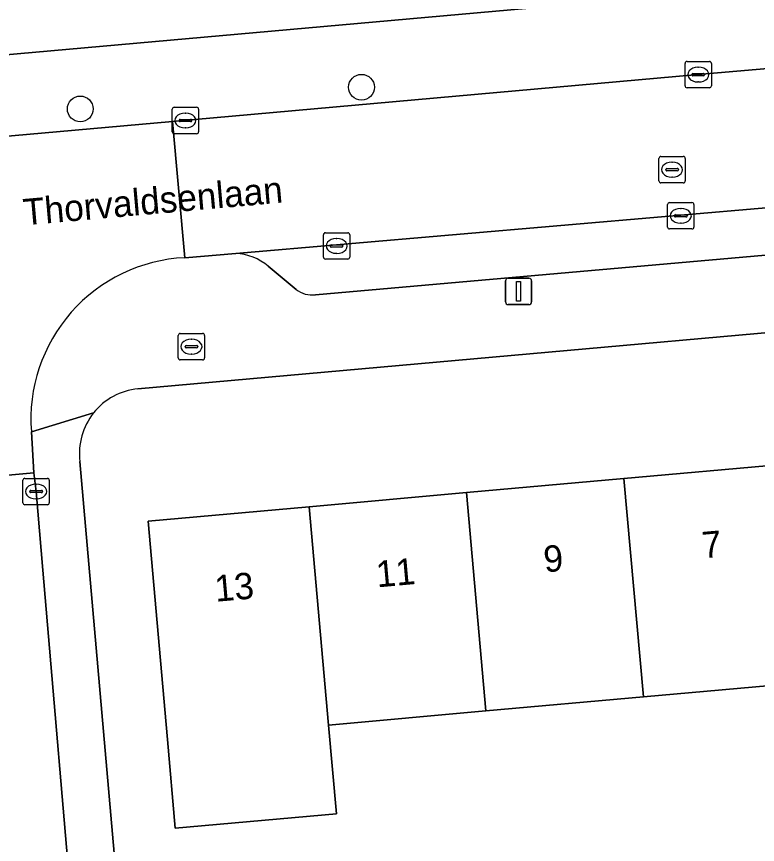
# Model space of a CAD drawing. Extents: x 160554 to 161248, y 385329 to 386506.
# Drawn here: x 161069.93 to 161098.06, y 385604.02 to 385635.43 of the extents above; entities that cross this region are included whole.
import ezdxf

# ---------------------------------------------------------------- set-up
doc = ezdxf.new("R2010")
doc.units = 0
for name, color, linetype in [('IMGEO_Boom', 7, 'Continuous'), ('IMGEO_Brandkraan', 7, 'Continuous'), ('IMGEO_Erf', 7, 'Continuous'), ('IMGEO_Kolk', 7, 'Continuous'), ('IMGEO_Lichtmast', 7, 'Continuous'), ('IMGEO_Openbare_ruimte_label', 7, 'Continuous'), ('IMGEO_Pand', 7, 'Continuous'), ('IMGEO_Pand_nummerreeks', 7, 'Continuous'), ('IMGEO_Parkeervlak_open', 7, 'Continuous'), ('IMGEO_Rijbaan_lokaal_open', 7, 'Continuous'), ('IMGEO_Rioolput', 7, 'Continuous'), ('IMGEO_Voetpad_open', 7, 'Continuous')]:
    doc.layers.add(name, color=color, linetype=linetype)

msp = doc.modelspace()

# ---------------------------------------------------------------- linework, layer by layer
at = {"layer": 'IMGEO_Boom'}
for centre in [(161083.027, 385632.744), (161072.352, 385631.921)]:
    msp.add_circle(centre, 0.489, dxfattribs=at)
at = {"layer": 'IMGEO_Brandkraan'}
for p, q in [((161076.071, 385622.476), (161076.071, 385623.328)), ((161076.146, 385623.402), (161076.998, 385623.402)), ((161076.559, 385623.182), (161076.584, 385623.182)), ((161077.072, 385623.328), (161077.072, 385622.476)), ((161076.33, 385622.896), (161076.33, 385622.908)), ((161076.373, 385622.945), (161076.771, 385622.945)), ((161076.814, 385622.908), (161076.814, 385622.896)), ((161076.768, 385622.859), (161076.37, 385622.859)), ((161076.582, 385622.622), (161076.557, 385622.622)), ((161076.998, 385622.402), (161076.146, 385622.402))]:
    msp.add_line(p, q, dxfattribs=at)
for points in [[(161076.071, 385622.476), (161076.071, 385623.328)], [(161076.146, 385623.402), (161076.998, 385623.402)], [(161077.072, 385623.328), (161077.072, 385622.476)], [(161076.998, 385622.402), (161076.146, 385622.402)]]:
    msp.add_lwpolyline(points, dxfattribs=at)
for centre, radius, start, end in [((161076.148, 385623.326), 0.0765, 91.552, 178.448), ((161076.148, 385623.326), 0.0765, 91.552, 178.448), ((161076.996, 385623.326), 0.0765, 1.552, 88.448), ((161076.996, 385623.326), 0.0765, 1.552, 88.448), ((161076.37, 385622.905), 0.0403, 85.8775, 175.7526), ((161076.367, 385622.895), 0.0366, 178.938, 274.7102), ((161076.771, 385622.902), 0.043, 264.8664, 352.4533), ((161076.775, 385622.907), 0.0386, 1.7309, 96.639), ((161076.148, 385622.478), 0.0765, 181.552, 268.448), ((161076.148, 385622.478), 0.0765, 181.552, 268.448), ((161076.996, 385622.478), 0.0765, 271.552, 358.448), ((161076.996, 385622.478), 0.0765, 271.552, 358.448)]:
    msp.add_arc(centre, radius, start, end, dxfattribs=at)
for centre, major_axis, ratio, start_param, end_param in [((161076.558, 385622.902), (-0.387, 0.002), 0.722429, 4.712389, 7.853982), ((161076.583, 385622.902), (-0.39, 0.002), 0.717154, 1.570796, 4.712389)]:
    msp.add_ellipse(centre, major_axis=major_axis, ratio=ratio, start_param=start_param, end_param=end_param, dxfattribs=at)
at = {"layer": 'IMGEO_Erf'}
for points in [[(161116.463, 385625.048), (161115.074, 385624.924), (161074.54, 385621.302)], [(161072.34, 385618.545), (161074.543, 385593.446)]]:
    msp.add_lwpolyline(points, dxfattribs=at)
msp.add_lwpolyline([(161093.728, 385609.619), (161087.752, 385609.085), (161081.776, 385608.551), (161082.077, 385605.183), (161075.957, 385604.636), (161075.661, 385608.005), (161075.611, 385608.572), (161074.933, 385616.289), (161081.037, 385616.833), (161087.013, 385617.366), (161092.989, 385617.899), (161098.966, 385618.431), (161104.942, 385618.964), (161110.918, 385619.497), (161117.024, 385620.041), (161117.763, 385611.765), (161111.657, 385611.22), (161105.681, 385610.686), (161105.995, 385607.167), (161100.019, 385606.633), (161099.705, 385610.152)], close=True, dxfattribs=at)
for centre, radius, start, end in [((161074.775, 385618.856), 2.457, 95.4806, 141.368), ((161074.773, 385618.86), 2.453, 141.4209, 187.3868)]:
    msp.add_arc(centre, radius, start, end, dxfattribs=at)
at = {"layer": 'IMGEO_Kolk'}
for p, q in [((161095.31, 385632.797), (161095.31, 385633.649)), ((161095.385, 385633.723), (161096.237, 385633.723)), ((161096.311, 385633.649), (161096.311, 385632.797)), ((161095.612, 385633.266), (161096.01, 385633.266)), ((161095.798, 385633.503), (161095.823, 385633.503)), ((161095.569, 385633.217), (161095.569, 385633.229)), ((161096.007, 385633.18), (161095.609, 385633.18)), ((161095.821, 385632.943), (161095.796, 385632.943)), ((161096.053, 385633.229), (161096.053, 385633.217)), ((161096.237, 385632.723), (161095.385, 385632.723)), ((161075.917, 385631.982), (161076.769, 385631.982)), ((161075.842, 385631.056), (161075.842, 385631.908)), ((161076.33, 385631.762), (161076.355, 385631.762)), ((161076.843, 385631.908), (161076.843, 385631.056)), ((161076.101, 385631.476), (161076.101, 385631.488)), ((161076.539, 385631.439), (161076.141, 385631.439)), ((161076.144, 385631.525), (161076.542, 385631.525)), ((161076.585, 385631.488), (161076.585, 385631.476)), ((161076.353, 385631.202), (161076.328, 385631.202)), ((161076.769, 385630.982), (161075.917, 385630.982)), ((161094.647, 385627.441), (161094.647, 385628.293)), ((161094.722, 385628.367), (161095.574, 385628.367)), ((161095.648, 385628.293), (161095.648, 385627.441)), ((161094.949, 385627.91), (161095.347, 385627.91)), ((161095.135, 385628.147), (161095.16, 385628.147)), ((161094.906, 385627.861), (161094.906, 385627.873)), ((161095.344, 385627.824), (161094.946, 385627.824)), ((161095.158, 385627.587), (161095.133, 385627.587)), ((161095.39, 385627.873), (161095.39, 385627.861)), ((161095.574, 385627.367), (161094.722, 385627.367)), ((161081.582, 385626.297), (161081.582, 385627.149)), ((161081.657, 385627.223), (161082.509, 385627.223)), ((161082.07, 385627.003), (161082.095, 385627.003)), ((161082.583, 385627.149), (161082.583, 385626.297)), ((161081.841, 385626.717), (161081.841, 385626.729)), ((161082.279, 385626.68), (161081.881, 385626.68)), ((161081.884, 385626.766), (161082.282, 385626.766)), ((161082.325, 385626.729), (161082.325, 385626.717)), ((161082.093, 385626.443), (161082.068, 385626.443)), ((161082.509, 385626.223), (161081.657, 385626.223)), ((161070.25, 385617.908), (161071.102, 385617.908)), ((161070.175, 385616.982), (161070.175, 385617.834)), ((161070.663, 385617.688), (161070.688, 385617.688)), ((161071.176, 385617.834), (161071.176, 385616.982)), ((161070.434, 385617.402), (161070.434, 385617.414)), ((161070.872, 385617.365), (161070.474, 385617.365)), ((161070.477, 385617.451), (161070.875, 385617.451)), ((161070.918, 385617.414), (161070.918, 385617.402)), ((161071.102, 385616.908), (161070.25, 385616.908)), ((161070.686, 385617.128), (161070.661, 385617.128))]:
    msp.add_line(p, q, dxfattribs=at)
for points in [[(161095.31, 385632.797), (161095.31, 385633.649)], [(161095.385, 385633.723), (161096.237, 385633.723)], [(161096.311, 385633.649), (161096.311, 385632.797)], [(161096.237, 385632.723), (161095.385, 385632.723)], [(161075.917, 385631.982), (161076.769, 385631.982)], [(161075.842, 385631.056), (161075.842, 385631.908)], [(161076.843, 385631.908), (161076.843, 385631.056)], [(161076.769, 385630.982), (161075.917, 385630.982)], [(161094.647, 385627.441), (161094.647, 385628.293)], [(161094.722, 385628.367), (161095.574, 385628.367)], [(161095.648, 385628.293), (161095.648, 385627.441)], [(161095.574, 385627.367), (161094.722, 385627.367)], [(161081.582, 385626.297), (161081.582, 385627.149)], [(161081.657, 385627.223), (161082.509, 385627.223)], [(161082.583, 385627.149), (161082.583, 385626.297)], [(161082.509, 385626.223), (161081.657, 385626.223)], [(161070.25, 385617.908), (161071.102, 385617.908)], [(161070.175, 385616.982), (161070.175, 385617.834)], [(161071.176, 385617.834), (161071.176, 385616.982)], [(161071.102, 385616.908), (161070.25, 385616.908)]]:
    msp.add_lwpolyline(points, dxfattribs=at)
for centre, radius, start, end in [((161095.387, 385633.647), 0.0765, 91.552, 178.448), ((161095.387, 385633.647), 0.0765, 91.552, 178.448), ((161096.235, 385633.647), 0.0765, 1.552, 88.448), ((161096.235, 385633.647), 0.0765, 1.552, 88.448), ((161095.609, 385633.226), 0.0403, 85.8775, 175.7526), ((161096.014, 385633.228), 0.0386, 1.7309, 96.639), ((161095.606, 385633.216), 0.0366, 178.938, 274.7102), ((161096.01, 385633.223), 0.043, 264.8664, 352.4533), ((161095.387, 385632.799), 0.0765, 181.552, 268.448), ((161095.387, 385632.799), 0.0765, 181.552, 268.448), ((161096.235, 385632.799), 0.0765, 271.552, 358.448), ((161096.235, 385632.799), 0.0765, 271.552, 358.448), ((161075.919, 385631.906), 0.0765, 91.552, 178.448), ((161075.919, 385631.906), 0.0765, 91.552, 178.448), ((161076.767, 385631.906), 0.0765, 1.552, 88.448), ((161076.767, 385631.906), 0.0765, 1.552, 88.448), ((161076.141, 385631.485), 0.0403, 85.8775, 175.7526), ((161076.138, 385631.475), 0.0366, 178.938, 274.7102), ((161076.542, 385631.482), 0.043, 264.8664, 352.4533), ((161076.546, 385631.487), 0.0386, 1.7309, 96.639), ((161075.919, 385631.058), 0.0765, 181.552, 268.448), ((161075.919, 385631.058), 0.0765, 181.552, 268.448), ((161076.767, 385631.058), 0.0765, 271.552, 358.448), ((161076.767, 385631.058), 0.0765, 271.552, 358.448), ((161094.724, 385628.291), 0.0765, 91.552, 178.448), ((161094.724, 385628.291), 0.0765, 91.552, 178.448), ((161095.572, 385628.291), 0.0765, 1.552, 88.448), ((161095.572, 385628.291), 0.0765, 1.552, 88.448), ((161094.946, 385627.87), 0.0403, 85.8775, 175.7526), ((161095.351, 385627.872), 0.0386, 1.7309, 96.639), ((161094.943, 385627.86), 0.0366, 178.938, 274.7102), ((161095.347, 385627.867), 0.043, 264.8664, 352.4533), ((161094.724, 385627.443), 0.0765, 181.552, 268.448), ((161094.724, 385627.443), 0.0765, 181.552, 268.448), ((161095.572, 385627.443), 0.0765, 271.552, 358.448), ((161095.572, 385627.443), 0.0765, 271.552, 358.448), ((161081.659, 385627.147), 0.0765, 91.552, 178.448), ((161081.659, 385627.147), 0.0765, 91.552, 178.448), ((161082.507, 385627.147), 0.0765, 1.552, 88.448), ((161082.507, 385627.147), 0.0765, 1.552, 88.448), ((161081.881, 385626.726), 0.0403, 85.8775, 175.7526), ((161081.878, 385626.716), 0.0366, 178.938, 274.7102), ((161082.282, 385626.723), 0.043, 264.8664, 352.4533), ((161082.286, 385626.728), 0.0386, 1.7309, 96.639), ((161081.659, 385626.299), 0.0765, 181.552, 268.448), ((161081.659, 385626.299), 0.0765, 181.552, 268.448), ((161082.507, 385626.299), 0.0765, 271.552, 358.448), ((161082.507, 385626.299), 0.0765, 271.552, 358.448), ((161070.252, 385617.832), 0.0765, 91.552, 178.448), ((161070.252, 385617.832), 0.0765, 91.552, 178.448), ((161071.1, 385617.832), 0.0765, 1.552, 88.448), ((161071.1, 385617.832), 0.0765, 1.552, 88.448), ((161070.474, 385617.411), 0.0403, 85.8775, 175.7526), ((161070.471, 385617.401), 0.0366, 178.938, 274.7102), ((161070.875, 385617.408), 0.043, 264.8664, 352.4533), ((161070.879, 385617.413), 0.0386, 1.7309, 96.639), ((161070.252, 385616.984), 0.0765, 181.552, 268.448), ((161070.252, 385616.984), 0.0765, 181.552, 268.448), ((161071.1, 385616.984), 0.0765, 271.552, 358.448), ((161071.1, 385616.984), 0.0765, 271.552, 358.448)]:
    msp.add_arc(centre, radius, start, end, dxfattribs=at)
for centre, major_axis, ratio, start_param, end_param in [((161095.797, 385633.223), (-0.387, 0.002), 0.722429, 4.712389, 7.853982), ((161095.822, 385633.223), (-0.39, 0.002), 0.717154, 1.570796, 4.712389), ((161076.329, 385631.482), (-0.387, 0.002), 0.722429, 4.712389, 7.853982), ((161076.354, 385631.482), (-0.39, 0.002), 0.717154, 1.570796, 4.712389), ((161095.134, 385627.867), (-0.387, 0.002), 0.722429, 4.712389, 7.853982), ((161095.159, 385627.867), (-0.39, 0.002), 0.717154, 1.570796, 4.712389), ((161082.069, 385626.723), (-0.387, 0.002), 0.722429, 4.712389, 7.853982), ((161082.094, 385626.723), (-0.39, 0.002), 0.717154, 1.570796, 4.712389), ((161070.662, 385617.408), (-0.387, 0.002), 0.722429, 4.712389, 7.853982), ((161070.687, 385617.408), (-0.39, 0.002), 0.717154, 1.570796, 4.712389)]:
    msp.add_ellipse(centre, major_axis=major_axis, ratio=ratio, start_param=start_param, end_param=end_param, dxfattribs=at)
at = {"layer": 'IMGEO_Lichtmast'}
for p, q in [((161088.493, 385624.599), (161088.493, 385625.399)), ((161088.493, 385625.399), (161088.493, 385624.599)), ((161088.593, 385625.499), (161089.383, 385625.499)), ((161089.383, 385625.499), (161088.593, 385625.499)), ((161089.483, 385625.399), (161089.483, 385624.599)), ((161089.483, 385624.599), (161089.483, 385625.399)), ((161089.383, 385624.499), (161088.593, 385624.499)), ((161088.593, 385624.499), (161089.383, 385624.499))]:
    msp.add_line(p, q, dxfattribs=at)
msp.add_lwpolyline([(161088.913, 385625.374), (161089.063, 385625.374), (161089.063, 385624.624), (161088.913, 385624.624), (161088.913, 385625.374)], dxfattribs=at)
for centre, start, end in [((161088.593, 385625.399), 90, 180), ((161088.593, 385625.399), 90, 180), ((161089.383, 385625.399), 0, 90), ((161089.383, 385625.399), 360, 90), ((161088.593, 385624.599), 180, 270), ((161088.593, 385624.599), 180, 270), ((161089.383, 385624.599), 270, 0), ((161089.383, 385624.599), 270, 0)]:
    msp.add_arc(centre, 0.1, start, end, dxfattribs=at)
at = {"layer": 'IMGEO_Pand'}
for points in [[(161093.728, 385609.619), (161099.705, 385610.152), (161098.966, 385618.431), (161092.989, 385617.899)], [(161092.989, 385617.899), (161087.013, 385617.366), (161087.752, 385609.085), (161093.728, 385609.619)], [(161087.013, 385617.366), (161081.037, 385616.833), (161081.776, 385608.551), (161087.752, 385609.085)], [(161081.037, 385616.833), (161074.933, 385616.289), (161075.611, 385608.572), (161075.661, 385608.005), (161075.957, 385604.636), (161082.077, 385605.183), (161081.776, 385608.551)]]:
    msp.add_lwpolyline(points, close=True, dxfattribs=at)
at = {"layer": 'IMGEO_Parkeervlak_open'}
for points in [[(161055.034, 385632.68), (161109.428, 385637.533), (161113.554, 385638.574), (161113.833, 385641.697), (161112.38, 385652.994), (161111.073, 385663.16), (161109.961, 385671.806), (161109.438, 385671.741), (161105.078, 385671.198), (161105.099, 385671.033), (161104.197, 385670.915), (161104.605, 385667.802), (161105.518, 385667.922), (161105.615, 385667.189), (161092.111, 385665.42), (161091.607, 385669.268), (161088.246, 385668.829), (161067.607, 385666.129), (161071.037, 385639.623), (161064.493, 385638.784)], [(161114.704, 385629.548), (161102.937, 385628.566), (161078.255, 385626.442)], [(161081.278, 385624.873), (161102.952, 385626.783), (161112.431, 385627.546)], [(161079.487, 385625.959), (161080.542, 385625.072)]]:
    msp.add_lwpolyline(points, dxfattribs=at)
for centre, radius, start, end in [((161078.12, 385624.284), 2.162, 50.7755, 86.4096), ((161081.152, 385625.869), 1.004, 232.5498, 277.1905)]:
    msp.add_arc(centre, radius, start, end, dxfattribs=at)
at = {"layer": 'IMGEO_Rijbaan_lokaal_open'}
msp.add_lwpolyline([(161115.047, 385634.843), (161111.237, 385634.506), (161102.409, 385633.794), (161095.811, 385633.223), (161075.852, 385631.439), (161076.316, 385626.277), (161078.255, 385626.442), (161102.937, 385628.566), (161114.704, 385629.548), (161114.846, 385629.57), (161115.569, 385629.617)], close=True, dxfattribs=at)
for points in [[(161076.316, 385626.277), (161075.852, 385631.439), (161056.224, 385629.703), (161056.723, 385624.518)], [(161063.442, 385619.201), (161063.655, 385617.485), (161070.591, 385618.12), (161070.495, 385619.676)], [(161070.927, 385614.424), (161070.675, 385617.407), (161070.591, 385618.12), (161063.655, 385617.485), (161063.712, 385617.074), (161064.234, 385611.073), (161071.552, 385527.169), (161071.554, 385527.151), (161071.555, 385527.133)], [(161074.538, 385572.239), (161070.927, 385614.424)]]:
    msp.add_lwpolyline(points, dxfattribs=at)
msp.add_arc((161076.614, 385620.147), 6.138, 92.787, 184.399, dxfattribs=at)
at = {"layer": 'IMGEO_Rioolput'}
for p, q in [((161094.392, 385630.117), (161095.244, 385630.117)), ((161094.317, 385629.191), (161094.317, 385630.043)), ((161094.805, 385629.897), (161094.83, 385629.897)), ((161095.318, 385630.043), (161095.318, 385629.191)), ((161094.576, 385629.611), (161094.576, 385629.623)), ((161095.014, 385629.574), (161094.616, 385629.574)), ((161094.619, 385629.66), (161095.017, 385629.66)), ((161095.06, 385629.623), (161095.06, 385629.611)), ((161094.828, 385629.337), (161094.803, 385629.337)), ((161095.244, 385629.117), (161094.392, 385629.117))]:
    msp.add_line(p, q, dxfattribs=at)
for points in [[(161094.392, 385630.117), (161095.244, 385630.117)], [(161094.317, 385629.191), (161094.317, 385630.043)], [(161095.318, 385630.043), (161095.318, 385629.191)], [(161095.244, 385629.117), (161094.392, 385629.117)]]:
    msp.add_lwpolyline(points, dxfattribs=at)
for centre, radius, start, end in [((161094.394, 385630.041), 0.0765, 91.552, 178.448), ((161094.394, 385630.041), 0.0765, 91.552, 178.448), ((161095.242, 385630.041), 0.0765, 1.552, 88.448), ((161095.242, 385630.041), 0.0765, 1.552, 88.448), ((161094.616, 385629.62), 0.0403, 85.8775, 175.7526), ((161094.613, 385629.61), 0.0366, 178.938, 274.7102), ((161095.017, 385629.617), 0.043, 264.8664, 352.4533), ((161095.021, 385629.622), 0.0386, 1.7309, 96.639), ((161094.394, 385629.193), 0.0765, 181.552, 268.448), ((161094.394, 385629.193), 0.0765, 181.552, 268.448), ((161095.242, 385629.193), 0.0765, 271.552, 358.448), ((161095.242, 385629.193), 0.0765, 271.552, 358.448)]:
    msp.add_arc(centre, radius, start, end, dxfattribs=at)
for centre, major_axis, ratio, start_param, end_param in [((161094.804, 385629.617), (-0.387, 0.002), 0.722429, 4.712389, 7.853982), ((161094.829, 385629.617), (-0.39, 0.002), 0.717154, 1.570796, 4.712389)]:
    msp.add_ellipse(centre, major_axis=major_axis, ratio=ratio, start_param=start_param, end_param=end_param, dxfattribs=at)
at = {"layer": 'IMGEO_Voetpad_open'}
msp.add_lwpolyline([(161113.833, 385641.697), (161113.554, 385638.574), (161109.428, 385637.533), (161055.034, 385632.68), (161055.294, 385629.619), (161056.224, 385629.703), (161075.852, 385631.439), (161095.811, 385633.223), (161102.409, 385633.794), (161111.237, 385634.506), (161115.047, 385634.843)], close=True, dxfattribs=at)
for points in [[(161112.431, 385627.546), (161102.952, 385626.783), (161081.278, 385624.873)], [(161078.255, 385626.442), (161076.316, 385626.277)], [(161080.542, 385625.072), (161079.487, 385625.959)], [(161074.54, 385621.302), (161115.074, 385624.924)], [(161072.855, 385620.39), (161070.495, 385619.676), (161070.591, 385618.12), (161070.675, 385617.407), (161070.927, 385614.424), (161074.538, 385572.239)], [(161070.495, 385619.676), (161072.855, 385620.39)], [(161074.681, 385591.873), (161074.543, 385593.446), (161072.34, 385618.545)]]:
    msp.add_lwpolyline(points, dxfattribs=at)
for centre, radius, start, end in [((161078.12, 385624.284), 2.162, 50.7755, 86.4096), ((161076.614, 385620.147), 6.138, 92.787, 184.399), ((161081.152, 385625.869), 1.004, 232.5498, 277.1905), ((161074.775, 385618.856), 2.457, 95.4806, 141.368), ((161074.773, 385618.86), 2.453, 141.4209, 187.3868)]:
    msp.add_arc(centre, radius, start, end, dxfattribs=at)

# ---------------------------------------------------------------- texts
at = {"layer": 'IMGEO_Openbare_ruimte_label'}
msp.add_text('Thorvaldsenlaan', height=1, rotation=5.0492, dxfattribs=at).set_placement((161070.226, 385627.503))
at = {"layer": 'IMGEO_Pand_nummerreeks'}
for s, rotation, p in [('7', 5.0939, (161095.995, 385614.873)), ('9', 5.0939, (161089.982, 385614.337)), ('11', 5.0939, (161083.625, 385613.77)), ('13', 5.0936, (161077.498, 385613.224))]:
    msp.add_text(s, height=1, rotation=rotation, dxfattribs=at).set_placement(p)

doc.saveas('drawing.dxf')
